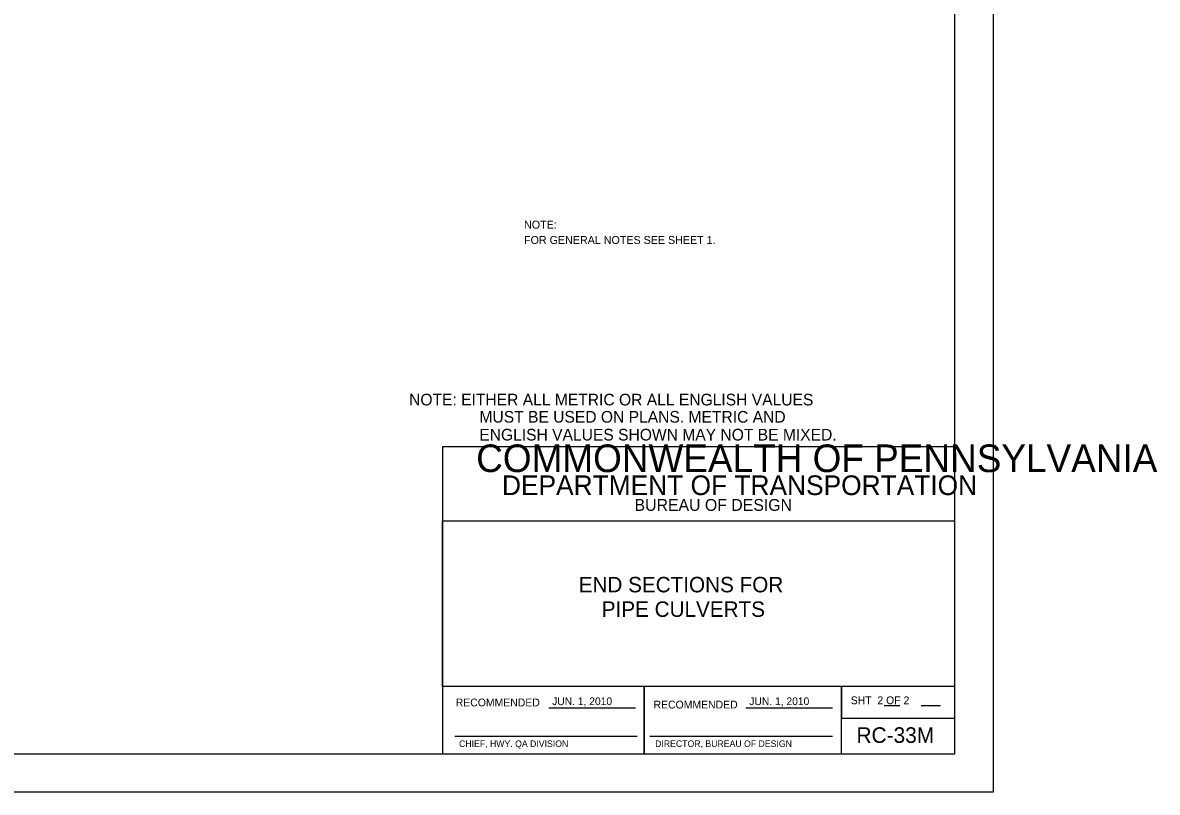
# Model space of a CAD drawing. Extents: x -17 to 888, y -473 to 715.
# Drawn here: x 444.9 to 887.9, y -473.1 to -172.4 of the extents above; entities that cross this region are included whole.
import ezdxf

# ---------------------------------------------------------------- set-up
doc = ezdxf.new("R2010")
doc.units = 0
for name, color, linetype in [('1', 7, 'Continuous'), ('2', 7, 'Continuous'), ('40', 7, 'Continuous'), ('PLT-BNDY', 7, 'Continuous')]:
    doc.layers.add(name, color=color, linetype=linetype)

msp = doc.modelspace()

# ---------------------------------------------------------------- linework, layer by layer
at = {"layer": '1'}
for p, q in [((650.26, -440.12), (684.15, -440.12)), ((727.26, -440.12), (761.13, -440.12)), ((781.25, -439.14), (787.39, -439.14)), ((795.66, -439.14), (803.31, -439.14)), ((613.56, -451.11), (684.81, -451.11)), ((689.73, -451.11), (761.07, -451.11))]:
    msp.add_line(p, q, dxfattribs=at)
msp.add_lwpolyline([(808.79, -458.11), (808.79, 105.89), (22.79, 105.89), (22.79, -458.11), (808.79, -458.11), (808.79, -431.75), (608.79, -431.75), (608.79, -367.07), (808.79, -367.07), (808.79, -338.11), (608.79, -338.11), (608.79, -458.11), (687.6, -458.11), (687.6, -431.75), (687.6, -458.11), (764.6, -458.11), (764.6, -431.75), (764.6, -444.07), (808.79, -444.07)], dxfattribs=at)
at = {"layer": 'PLT-BNDY'}
msp.add_lwpolyline([(-17.21, 120.89), (823.79, 120.89), (823.79, -473.11), (-17.21, -473.11)], close=True, dxfattribs=at)

# ---------------------------------------------------------------- texts
at = {"layer": '1'}
for s, height, p in [('COMMONWEALTH OF PENNSYLVANIA', 10.7834, (621.94, -347.97)), ('DEPARTMENT OF TRANSPORTATION', 7.6843, (632.01, -356.96)), ('BUREAU OF DESIGN', 4.6221, (683.78, -363.12)), ('END SECTIONS FOR', 6.04, (661.97, -394.96)), ('PIPE CULVERTS', 6.04, (670.98, -404.55)), ('RECOMMENDED', 3.048, (613.96, -439.52)), ('JUN. 1, 2010', 3, (651.6, -439.03)), ('RECOMMENDED', 3.048, (691.2, -440.35)), ('JUN. 1, 2010', 3, (728.6, -439.03)), ('SHT  2 OF 2', 3.048, (768.2, -438.68)), ('APPROVED', 0.0192, (651.82, -440.18)), ('RC-33M', 6.096, (770.44, -453.79)), ('CHIEF, HWY. QA DIVISION ', 2.54, (615.25, -455.37)), ('DIRECTOR, BUREAU OF DESIGN', 2.54, (691.82, -455.37))]:
    msp.add_text(s, height=height, dxfattribs=at).set_placement(p)
at = {"layer": '2'}
for s, p in [('NOTE:', (640.63, -252.84)), ('FOR GENERAL NOTES SEE SHEET 1.', (640.63, -258.84))]:
    msp.add_text(s, height=3.126, dxfattribs=at).set_placement(p)
at = {"layer": '40'}
for s, p in [('NOTE: EITHER ALL METRIC OR ALL ENGLISH VALUES', (595.74, -321.93)), ('MUST BE USED ON PLANS. METRIC AND', (623.22, -328.65)), ('ENGLISH VALUES SHOWN MAY NOT BE MIXED.', (623.15, -335.63))]:
    msp.add_text(s, height=4.5587, dxfattribs=at).set_placement(p)

doc.saveas('drawing.dxf')
